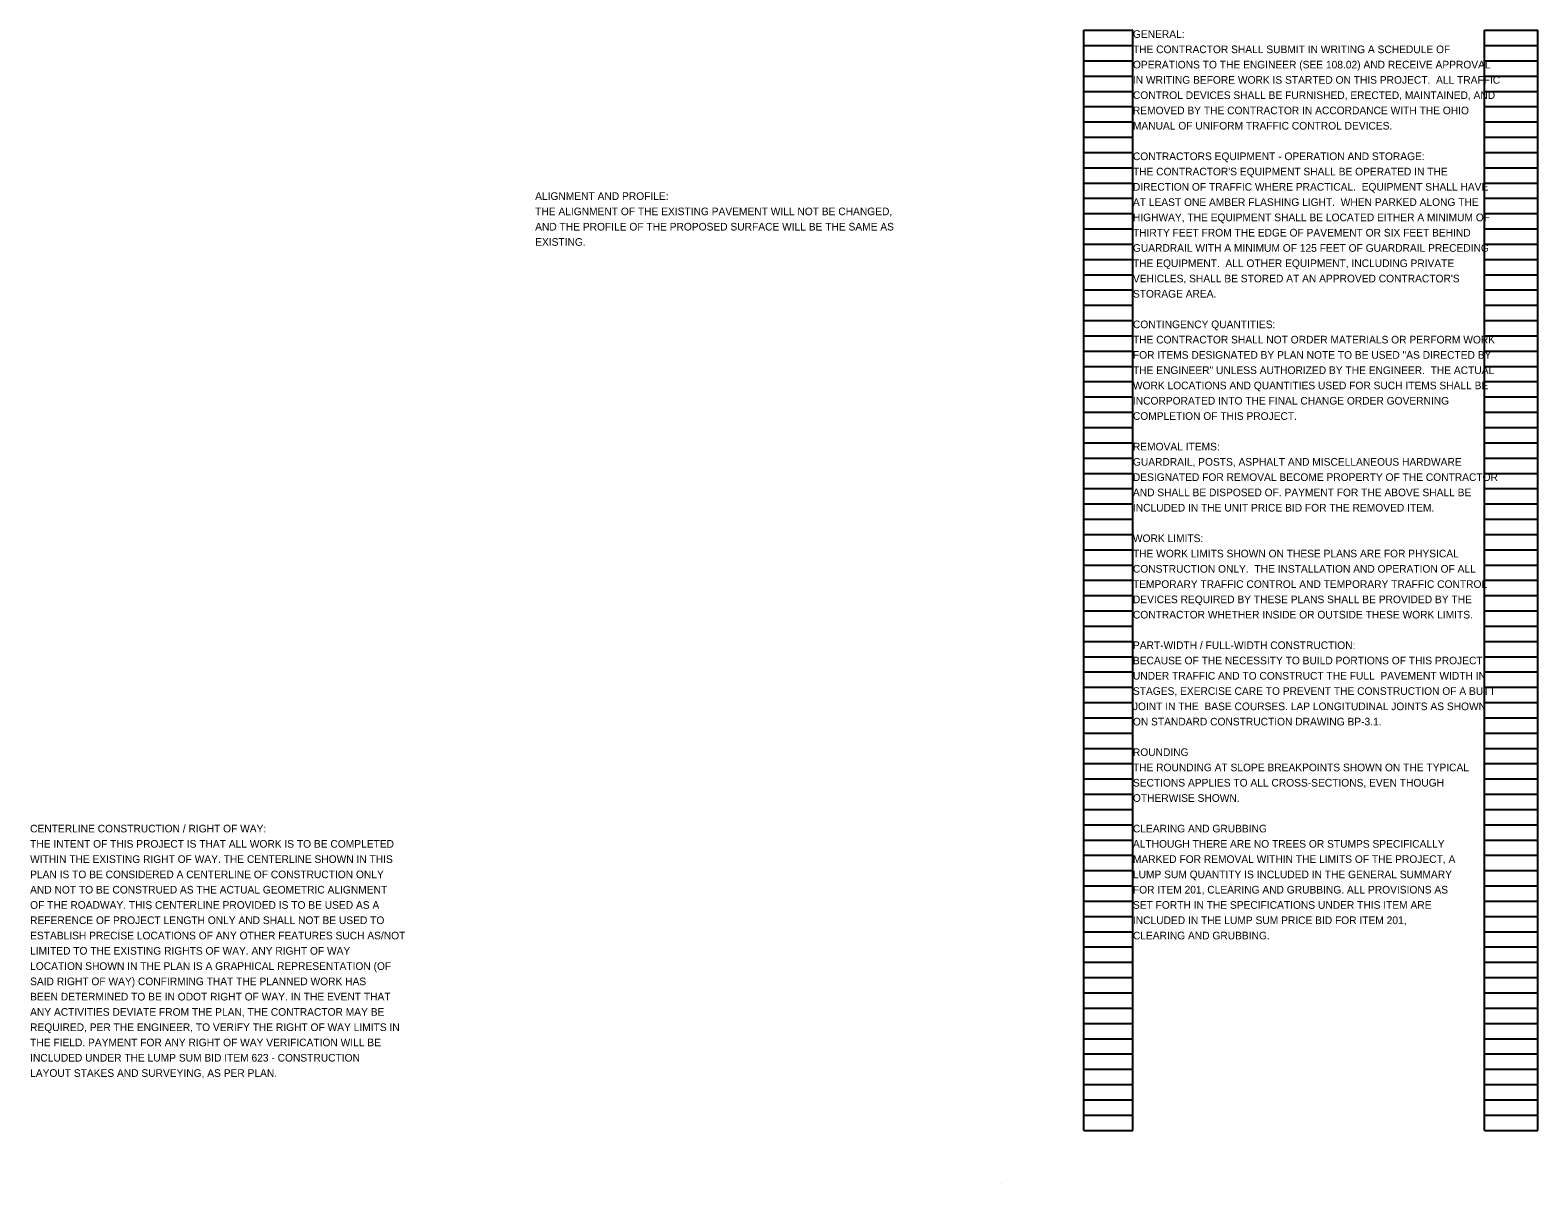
# Model space of a CAD drawing. Extents: x 28758.7 to 28808.5, y 9178.8 to 9230.7.
# Drawn here: x 28758.72 to 28786.35, y 9209.6 to 9230.74 of the extents above; entities that cross this region are included whole.
import ezdxf

# ---------------------------------------------------------------- set-up
doc = ezdxf.new("R2010")
doc.units = 0
doc.layers.add('SH_Data', color=7, linetype='Continuous')
doc.layers.add('SH_Text', color=7, linetype='Continuous')

msp = doc.modelspace()

# ---------------------------------------------------------------- linework, layer by layer
at = {"layer": 'SH_Text'}
for p, q in [((28778.029, 9210.582), (28778.029, 9230.742)), ((28778.029, 9230.742), (28778.929, 9230.742)), ((28778.929, 9210.582), (28778.929, 9230.742)), ((28785.369, 9210.582), (28785.369, 9230.742)), ((28785.369, 9230.742), (28786.349, 9230.742)), ((28786.349, 9210.582), (28786.349, 9230.742)), ((28778.029, 9230.462), (28778.929, 9230.462)), ((28785.369, 9230.462), (28786.349, 9230.462)), ((28778.029, 9230.182), (28778.929, 9230.182)), ((28785.369, 9230.182), (28786.349, 9230.182)), ((28778.029, 9229.902), (28778.929, 9229.902)), ((28785.369, 9229.902), (28786.349, 9229.902)), ((28778.029, 9229.622), (28778.929, 9229.622)), ((28785.369, 9229.622), (28786.349, 9229.622)), ((28778.029, 9229.342), (28778.929, 9229.342)), ((28785.369, 9229.342), (28786.349, 9229.342)), ((28778.029, 9229.062), (28778.929, 9229.062)), ((28785.369, 9229.062), (28786.349, 9229.062)), ((28778.029, 9228.782), (28778.929, 9228.782)), ((28785.369, 9228.782), (28786.349, 9228.782)), ((28778.029, 9228.502), (28778.929, 9228.502)), ((28785.369, 9228.502), (28786.349, 9228.502)), ((28778.029, 9228.222), (28778.929, 9228.222)), ((28785.369, 9228.222), (28786.349, 9228.222)), ((28778.029, 9227.942), (28778.929, 9227.942)), ((28785.369, 9227.942), (28786.349, 9227.942)), ((28778.029, 9227.662), (28778.929, 9227.662)), ((28785.369, 9227.662), (28786.349, 9227.662)), ((28778.029, 9227.382), (28778.929, 9227.382)), ((28785.369, 9227.382), (28786.349, 9227.382)), ((28778.029, 9227.102), (28778.929, 9227.102)), ((28785.369, 9227.102), (28786.349, 9227.102)), ((28778.029, 9226.822), (28778.929, 9226.822)), ((28785.369, 9226.822), (28786.349, 9226.822)), ((28778.029, 9226.542), (28778.929, 9226.542)), ((28785.369, 9226.542), (28786.349, 9226.542)), ((28778.029, 9226.262), (28778.929, 9226.262)), ((28785.369, 9226.262), (28786.349, 9226.262)), ((28778.029, 9225.982), (28778.929, 9225.982)), ((28785.369, 9225.982), (28786.349, 9225.982)), ((28778.029, 9225.702), (28778.929, 9225.702)), ((28785.369, 9225.702), (28786.349, 9225.702)), ((28778.029, 9225.422), (28778.929, 9225.422)), ((28785.369, 9225.422), (28786.349, 9225.422)), ((28778.029, 9225.142), (28778.929, 9225.142)), ((28785.369, 9225.142), (28786.349, 9225.142)), ((28778.029, 9224.862), (28778.929, 9224.862)), ((28785.369, 9224.862), (28786.349, 9224.862)), ((28778.029, 9224.582), (28778.929, 9224.582)), ((28785.369, 9224.582), (28786.349, 9224.582)), ((28778.029, 9224.302), (28778.929, 9224.302)), ((28785.369, 9224.302), (28786.349, 9224.302)), ((28778.029, 9224.022), (28778.929, 9224.022)), ((28785.369, 9224.022), (28786.349, 9224.022)), ((28778.029, 9223.742), (28778.929, 9223.742)), ((28785.369, 9223.742), (28786.349, 9223.742)), ((28778.029, 9223.462), (28778.929, 9223.462)), ((28785.369, 9223.462), (28786.349, 9223.462)), ((28778.029, 9223.182), (28778.929, 9223.182)), ((28785.369, 9223.182), (28786.349, 9223.182)), ((28778.029, 9222.902), (28778.929, 9222.902)), ((28785.369, 9222.902), (28786.349, 9222.902)), ((28778.029, 9222.622), (28778.929, 9222.622)), ((28785.369, 9222.622), (28786.349, 9222.622)), ((28778.029, 9222.342), (28778.929, 9222.342)), ((28785.369, 9222.342), (28786.349, 9222.342)), ((28778.029, 9222.062), (28778.929, 9222.062)), ((28785.369, 9222.062), (28786.349, 9222.062)), ((28778.029, 9221.782), (28778.929, 9221.782)), ((28785.369, 9221.782), (28786.349, 9221.782)), ((28778.029, 9221.502), (28778.929, 9221.502)), ((28785.369, 9221.502), (28786.349, 9221.502)), ((28778.029, 9221.222), (28778.929, 9221.222)), ((28785.369, 9221.222), (28786.349, 9221.222)), ((28778.029, 9220.942), (28778.929, 9220.942)), ((28785.369, 9220.942), (28786.349, 9220.942)), ((28778.029, 9220.662), (28778.929, 9220.662)), ((28785.369, 9220.662), (28786.349, 9220.662)), ((28778.029, 9220.382), (28778.929, 9220.382)), ((28785.369, 9220.382), (28786.349, 9220.382)), ((28778.029, 9220.102), (28778.929, 9220.102)), ((28785.369, 9220.102), (28786.349, 9220.102)), ((28778.029, 9219.822), (28778.929, 9219.822)), ((28785.369, 9219.822), (28786.349, 9219.822)), ((28778.029, 9219.542), (28778.929, 9219.542)), ((28785.369, 9219.542), (28786.349, 9219.542)), ((28778.029, 9219.262), (28778.929, 9219.262)), ((28785.369, 9219.262), (28786.349, 9219.262)), ((28778.029, 9218.982), (28778.929, 9218.982)), ((28785.369, 9218.982), (28786.349, 9218.982)), ((28778.029, 9218.702), (28778.929, 9218.702)), ((28785.369, 9218.702), (28786.349, 9218.702)), ((28778.029, 9218.422), (28778.929, 9218.422)), ((28785.369, 9218.422), (28786.349, 9218.422)), ((28778.029, 9218.142), (28778.929, 9218.142)), ((28785.369, 9218.142), (28786.349, 9218.142)), ((28778.029, 9217.862), (28778.929, 9217.862)), ((28785.369, 9217.862), (28786.349, 9217.862)), ((28778.029, 9217.582), (28778.929, 9217.582)), ((28785.369, 9217.582), (28786.349, 9217.582)), ((28778.029, 9217.302), (28778.929, 9217.302)), ((28785.369, 9217.302), (28786.349, 9217.302)), ((28778.029, 9217.022), (28778.929, 9217.022)), ((28785.369, 9217.022), (28786.349, 9217.022)), ((28778.029, 9216.742), (28778.929, 9216.742)), ((28785.369, 9216.742), (28786.349, 9216.742)), ((28778.029, 9216.462), (28778.929, 9216.462)), ((28785.369, 9216.462), (28786.349, 9216.462)), ((28778.029, 9216.182), (28778.929, 9216.182)), ((28785.369, 9216.182), (28786.349, 9216.182)), ((28778.029, 9215.902), (28778.929, 9215.902)), ((28785.369, 9215.902), (28786.349, 9215.902)), ((28778.029, 9215.622), (28778.929, 9215.622)), ((28785.369, 9215.622), (28786.349, 9215.622)), ((28778.029, 9215.342), (28778.929, 9215.342)), ((28785.369, 9215.342), (28786.349, 9215.342)), ((28778.029, 9215.062), (28778.929, 9215.062)), ((28785.369, 9215.062), (28786.349, 9215.062)), ((28778.029, 9214.782), (28778.929, 9214.782)), ((28785.369, 9214.782), (28786.349, 9214.782)), ((28778.029, 9214.502), (28778.929, 9214.502)), ((28785.369, 9214.502), (28786.349, 9214.502)), ((28778.029, 9214.222), (28778.929, 9214.222)), ((28785.369, 9214.222), (28786.349, 9214.222)), ((28778.029, 9213.942), (28778.929, 9213.942)), ((28785.369, 9213.942), (28786.349, 9213.942)), ((28778.029, 9213.662), (28778.929, 9213.662)), ((28785.369, 9213.662), (28786.349, 9213.662)), ((28778.029, 9213.382), (28778.929, 9213.382)), ((28785.369, 9213.382), (28786.349, 9213.382)), ((28778.029, 9213.102), (28778.929, 9213.102)), ((28785.369, 9213.102), (28786.349, 9213.102)), ((28778.029, 9212.822), (28778.929, 9212.822)), ((28785.369, 9212.822), (28786.349, 9212.822)), ((28778.029, 9212.542), (28778.929, 9212.542)), ((28785.369, 9212.542), (28786.349, 9212.542)), ((28778.029, 9212.262), (28778.929, 9212.262)), ((28785.369, 9212.262), (28786.349, 9212.262)), ((28778.029, 9211.982), (28778.929, 9211.982)), ((28785.369, 9211.982), (28786.349, 9211.982)), ((28778.029, 9211.702), (28778.929, 9211.702)), ((28785.369, 9211.702), (28786.349, 9211.702)), ((28778.029, 9211.422), (28778.929, 9211.422)), ((28785.369, 9211.422), (28786.349, 9211.422)), ((28778.029, 9211.142), (28778.929, 9211.142)), ((28785.369, 9211.142), (28786.349, 9211.142)), ((28778.029, 9210.862), (28778.929, 9210.862)), ((28785.369, 9210.862), (28786.349, 9210.862)), ((28778.029, 9210.582), (28778.929, 9210.582)), ((28785.369, 9210.582), (28786.349, 9210.582)), ((28776.529, 9209.602), (28776.529, 9209.602))]:
    msp.add_line(p, q, dxfattribs=at)

# ---------------------------------------------------------------- texts
at = {"layer": 'SH_Data'}
for s, p in [('GENERAL:', (28778.929, 9230.602)), ('THE CONTRACTOR SHALL SUBMIT IN WRITING A SCHEDULE OF ', (28778.929, 9230.322)), ('OPERATIONS TO THE ENGINEER (SEE 108.02) AND RECEIVE APPROVAL ', (28778.929, 9230.042)), ('IN WRITING BEFORE WORK IS STARTED ON THIS PROJECT.  ALL TRAFFIC ', (28778.929, 9229.762)), ('CONTROL DEVICES SHALL BE FURNISHED, ERECTED, MAINTAINED, AND ', (28778.929, 9229.482)), ('REMOVED BY THE CONTRACTOR IN ACCORDANCE WITH THE OHIO ', (28778.929, 9229.202)), ('MANUAL OF UNIFORM TRAFFIC CONTROL DEVICES.', (28778.929, 9228.922)), ('CONTRACTORS EQUIPMENT - OPERATION AND STORAGE:', (28778.929, 9228.362)), ("THE CONTRACTOR'S EQUIPMENT SHALL BE OPERATED IN THE ", (28778.929, 9228.082)), ('DIRECTION OF TRAFFIC WHERE PRACTICAL.  EQUIPMENT SHALL HAVE ', (28778.929, 9227.802)), ('ALIGNMENT AND PROFILE:', (28767.976, 9227.632)), ('AT LEAST ONE AMBER FLASHING LIGHT.  WHEN PARKED ALONG THE ', (28778.929, 9227.522)), ('THE ALIGNMENT OF THE EXISTING PAVEMENT WILL NOT BE CHANGED, ', (28767.976, 9227.352)), ('HIGHWAY, THE EQUIPMENT SHALL BE LOCATED EITHER A MINIMUM OF ', (28778.929, 9227.242)), ('AND THE PROFILE OF THE PROPOSED SURFACE WILL BE THE SAME AS ', (28767.976, 9227.072)), ('THIRTY FEET FROM THE EDGE OF PAVEMENT OR SIX FEET BEHIND ', (28778.929, 9226.962)), ('EXISTING. ', (28767.976, 9226.792)), ('GUARDRAIL WITH A MINIMUM OF 125 FEET OF GUARDRAIL PRECEDING ', (28778.929, 9226.682)), ('THE EQUIPMENT.  ALL OTHER EQUIPMENT, INCLUDING PRIVATE ', (28778.929, 9226.402)), ("VEHICLES, SHALL BE STORED AT AN APPROVED CONTRACTOR'S ", (28778.929, 9226.122)), ('STORAGE AREA.', (28778.929, 9225.842)), ('CONTINGENCY QUANTITIES:', (28778.929, 9225.282)), ('THE CONTRACTOR SHALL NOT ORDER MATERIALS OR PERFORM WORK ', (28778.929, 9225.002)), ('FOR ITEMS DESIGNATED BY PLAN NOTE TO BE USED "AS DIRECTED BY ', (28778.929, 9224.722)), ('THE ENGINEER" UNLESS AUTHORIZED BY THE ENGINEER.  THE ACTUAL ', (28778.929, 9224.442)), ('WORK LOCATIONS AND QUANTITIES USED FOR SUCH ITEMS SHALL BE ', (28778.929, 9224.162)), ('INCORPORATED INTO THE FINAL CHANGE ORDER GOVERNING ', (28778.929, 9223.882)), ('COMPLETION OF THIS PROJECT.', (28778.929, 9223.602)), ('REMOVAL ITEMS:', (28778.929, 9223.042)), ('GUARDRAIL, POSTS, ASPHALT AND MISCELLANEOUS HARDWARE ', (28778.929, 9222.762)), ('DESIGNATED FOR REMOVAL BECOME PROPERTY OF THE CONTRACTOR ', (28778.929, 9222.482)), ('AND SHALL BE DISPOSED OF. PAYMENT FOR THE ABOVE SHALL BE ', (28778.929, 9222.202)), ('INCLUDED IN THE UNIT PRICE BID FOR THE REMOVED ITEM.', (28778.929, 9221.922)), ('WORK LIMITS:', (28778.929, 9221.362)), ('THE WORK LIMITS SHOWN ON THESE PLANS ARE FOR PHYSICAL ', (28778.929, 9221.082)), ('CONSTRUCTION ONLY.  THE INSTALLATION AND OPERATION OF ALL ', (28778.929, 9220.802)), ('TEMPORARY TRAFFIC CONTROL AND TEMPORARY TRAFFIC CONTROL ', (28778.929, 9220.522)), ('DEVICES REQUIRED BY THESE PLANS SHALL BE PROVIDED BY THE ', (28778.929, 9220.242)), ('CONTRACTOR WHETHER INSIDE OR OUTSIDE THESE WORK LIMITS.', (28778.929, 9219.962)), ('PART-WIDTH / FULL-WIDTH CONSTRUCTION:', (28778.929, 9219.402)), ('BECAUSE OF THE NECESSITY TO BUILD PORTIONS OF THIS PROJECT ', (28778.929, 9219.122)), ('UNDER TRAFFIC AND TO CONSTRUCT THE FULL  PAVEMENT WIDTH IN ', (28778.929, 9218.842)), ('STAGES, EXERCISE CARE TO PREVENT THE CONSTRUCTION OF A BUTT ', (28778.929, 9218.562)), ('JOINT IN THE  BASE COURSES. LAP LONGITUDINAL JOINTS AS SHOWN ', (28778.929, 9218.282)), ('ON STANDARD CONSTRUCTION DRAWING BP-3.1.', (28778.929, 9218.002)), ('ROUNDING', (28778.929, 9217.442)), ('THE ROUNDING AT SLOPE BREAKPOINTS SHOWN ON THE TYPICAL', (28778.929, 9217.162)), ('SECTIONS APPLIES TO ALL CROSS-SECTIONS, EVEN THOUGH', (28778.929, 9216.882)), ('OTHERWISE SHOWN.', (28778.929, 9216.602)), ('CENTERLINE CONSTRUCTION / RIGHT OF WAY:', (28758.722, 9216.042)), ('CLEARING AND GRUBBING', (28778.929, 9216.042)), ('THE INTENT OF THIS PROJECT IS THAT ALL WORK IS TO BE COMPLETED ', (28758.722, 9215.762)), ('ALTHOUGH THERE ARE NO TREES OR STUMPS SPECIFICALLY', (28778.929, 9215.762)), ('WITHIN THE EXISTING RIGHT OF WAY. THE CENTERLINE SHOWN IN THIS ', (28758.722, 9215.482)), ('MARKED FOR REMOVAL WITHIN THE LIMITS OF THE PROJECT, A', (28778.929, 9215.482)), ('PLAN IS TO BE CONSIDERED A CENTERLINE OF CONSTRUCTION ONLY ', (28758.722, 9215.202)), ('LUMP SUM QUANTITY IS INCLUDED IN THE GENERAL SUMMARY', (28778.929, 9215.202)), ('AND NOT TO BE CONSTRUED AS THE ACTUAL GEOMETRIC ALIGNMENT ', (28758.722, 9214.922)), ('FOR ITEM 201, CLEARING AND GRUBBING. ALL PROVISIONS AS', (28778.929, 9214.922)), ('OF THE ROADWAY. THIS CENTERLINE PROVIDED IS TO BE USED AS A ', (28758.722, 9214.642)), ('SET FORTH IN THE SPECIFICATIONS UNDER THIS ITEM ARE', (28778.929, 9214.642)), ('REFERENCE OF PROJECT LENGTH ONLY AND SHALL NOT BE USED TO ', (28758.722, 9214.362)), ('INCLUDED IN THE LUMP SUM PRICE BID FOR ITEM 201, ', (28778.929, 9214.362)), ('ESTABLISH PRECISE LOCATIONS OF ANY OTHER FEATURES SUCH AS/NOT ', (28758.722, 9214.082)), ('CLEARING AND GRUBBING.', (28778.929, 9214.082)), ('LIMITED TO THE EXISTING RIGHTS OF WAY. ANY RIGHT OF WAY ', (28758.722, 9213.802)), ('LOCATION SHOWN IN THE PLAN IS A GRAPHICAL REPRESENTATION (OF ', (28758.722, 9213.522)), ('SAID RIGHT OF WAY) CONFIRMING THAT THE PLANNED WORK HAS ', (28758.722, 9213.242)), ('BEEN DETERMINED TO BE IN ODOT RIGHT OF WAY. IN THE EVENT THAT ', (28758.722, 9212.962)), ('ANY ACTIVITIES DEVIATE FROM THE PLAN, THE CONTRACTOR MAY BE ', (28758.722, 9212.682)), ('REQUIRED, PER THE ENGINEER, TO VERIFY THE RIGHT OF WAY LIMITS IN ', (28758.722, 9212.402)), ('THE FIELD. PAYMENT FOR ANY RIGHT OF WAY VERIFICATION WILL BE ', (28758.722, 9212.122)), ('INCLUDED UNDER THE LUMP SUM BID ITEM 623 - CONSTRUCTION ', (28758.722, 9211.842)), ('LAYOUT STAKES AND SURVEYING, AS PER PLAN.', (28758.722, 9211.562))]:
    msp.add_text(s, height=0.14, dxfattribs=at).set_placement(p)

doc.saveas('drawing.dxf')
